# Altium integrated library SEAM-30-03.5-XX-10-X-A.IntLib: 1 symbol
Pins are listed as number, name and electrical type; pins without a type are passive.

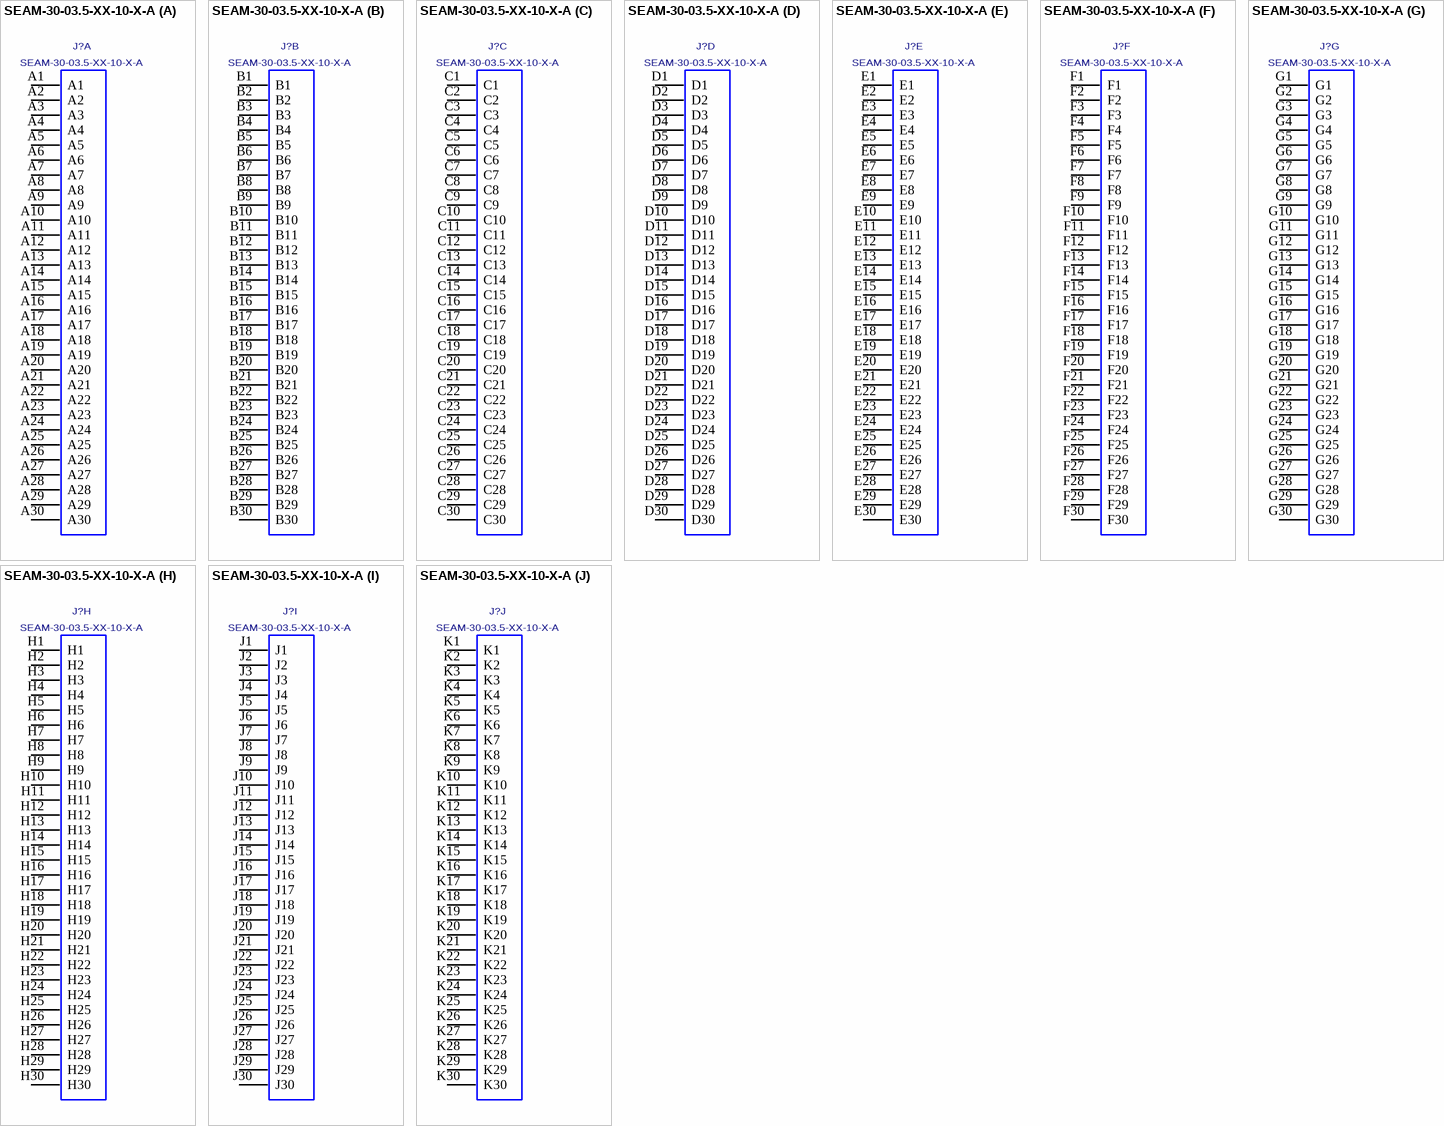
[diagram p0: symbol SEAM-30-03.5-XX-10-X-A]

## SEAM-30-03.5-XX-10-X-A
designator J?
Terminal Array Assembly, Surface Mount, 0.050" Pitch,300 Pins; MANUFACTURER: SAMTEC
footprint SEAM-30-03.5-XX-10-X-A
part A pins: A1, A2, A3, A4, A5, A6, A7, A8, A9, A10, A11, A12, A13, A14, A15, A16, A17, A18, A19, A20, A21, A22, A23, A24, A25, A26, A27, A28, A29, A30
part B pins: B1, B2, B3, B4, B5, B6, B7, B8, B9, B10, B11, B12, B13, B14, B15, B16, B17, B18, B19, B20, B21, B22, B23, B24, B25, B26, B27, B28, B29, B30
part C pins: C1, C2, C3, C4, C5, C6, C7, C8, C9, C10, C11, C12, C13, C14, C15, C16, C17, C18, C19, C20, C21, C22, C23, C24, C25, C26, C27, C28, C29, C30
part D pins: D1, D2, D3, D4, D5, D6, D7, D8, D9, D10, D11, D12, D13, D14, D15, D16, D17, D18, D19, D20, D21, D22, D23, D24, D25, D26, D27, D28, D29, D30
part E pins: E1, E2, E3, E4, E5, E6, E7, E8, E9, E10, E11, E12, E13, E14, E15, E16, E17, E18, E19, E20, E21, E22, E23, E24, E25, E26, E27, E28, E29, E30
part F pins: F1, F2, F3, F4, F5, F6, F7, F8, F9, F10, F11, F12, F13, F14, F15, F16, F17, F18, F19, F20, F21, F22, F23, F24, F25, F26, F27, F28, F29, F30
part G pins: G1, G2, G3, G4, G5, G6, G7, G8, G9, G10, G11, G12, G13, G14, G15, G16, G17, G18, G19, G20, G21, G22, G23, G24, G25, G26, G27, G28, G29, G30
part H pins: H1, H2, H3, H4, H5, H6, H7, H8, H9, H10, H11, H12, H13, H14, H15, H16, H17, H18, H19, H20, H21, H22, H23, H24, H25, H26, H27, H28, H29, H30
part I pins: J1, J2, J3, J4, J5, J6, J7, J8, J9, J10, J11, J12, J13, J14, J15, J16, J17, J18, J19, J20, J21, J22, J23, J24, J25, J26, J27, J28, J29, J30
part J pins: K1, K2, K3, K4, K5, K6, K7, K8, K9, K10, K11, K12, K13, K14, K15, K16, K17, K18, K19, K20, K21, K22, K23, K24, K25, K26, K27, K28, K29, K30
